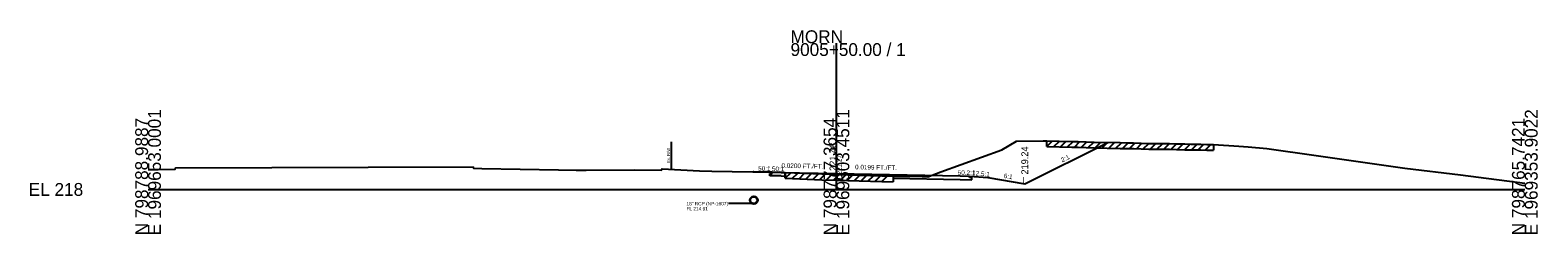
# Model space of a CAD drawing. Extents: x -26 to 2313, y -1511 to 5559.
# Drawn here: x -25.7 to 302.8, y 3490.3 to 3534.7 of the extents above; entities that cross this region are included whole.
import ezdxf

# ---------------------------------------------------------------- set-up
doc = ezdxf.new("R2010")
doc.units = 0
for name, color, linetype in [('RD_GPK_XS_Cell', 7, 'Continuous'), ('RD_XS_Base', 7, 'Continuous'), ('RD_XS_EarthShd', 7, 'Continuous'), ('RD_XS_ExGround', 7, 'Continuous'), ('RD_XS_ExPaveRet', 7, 'Continuous'), ('RD_XS_ExRW', 7, 'Continuous'), ('RD_XS_Misc_Line', 7, 'Continuous'), ('RD_XS_Pave', 7, 'Continuous'), ('RD_XS_PaveOvlay', 7, 'Continuous'), ('RD_XS_PaveShd', 7, 'Continuous'), ('RD_XS_Pipe', 7, 'Continuous'), ('RD_XS_TieSlope', 7, 'Continuous'), ('RD_XS_TX_Elev_EX', 7, 'Continuous'), ('RD_XS_TX_Elev_PR', 7, 'Continuous'), ('RD_XS_TX_Misc', 7, 'Continuous'), ('RD_XS_TX_MkPT', 7, 'Continuous'), ('RD_XS_TX_Profile', 7, 'Continuous'), ('RD_XS_TX_ShdSlope', 7, 'Continuous'), ('RD_XS_TX_Slope', 7, 'Continuous')]:
    doc.layers.add(name, color=color, linetype=linetype)

msp = doc.modelspace()

# ---------------------------------------------------------------- linework, layer by layer
at = {"layer": 'RD_GPK_XS_Cell'}
for p, q in [((150, 3500), (150, 3531.9)), ((0, 3500), (150, 3500)), ((150, 3500), (300, 3500))]:
    msp.add_line(p, q, dxfattribs=at)
at = {"layer": 'RD_XS_Base'}
for p, q in [((135.49, 3503.47), (135.99, 3503.46)), ((135.49, 3502.99), (135.49, 3503.47)), ((137.99, 3502.94), (135.49, 3502.99)), ((135.99, 3503.46), (135.99, 3503.76)), ((179, 3502.6), (179, 3502.9)), ((179.5, 3502.59), (179, 3502.6)), ((179.5, 3502.11), (179.5, 3502.59)), ((176.99, 3502.16), (179.5, 3502.11))]:
    msp.add_line(p, q, dxfattribs=at)
at = {"layer": 'RD_XS_EarthShd'}
for p, q in [((135.99, 3503.76), (131.99, 3503.84)), ((179, 3502.9), (183.01, 3502.58))]:
    msp.add_line(p, q, dxfattribs=at)
at = {"layer": 'RD_XS_ExGround'}
msp.add_lwpolyline([(0, 3504.36), (2.1, 3504.37), (5.88, 3504.41), (5.98, 3504.71), (47.94, 3504.84), (70.81, 3504.91), (70.91, 3504.61), (72.71, 3504.55), (89.45, 3504.3), (93.28, 3504.23), (95.43, 3504.22), (106.03, 3504.24), (111.89, 3504.18), (111.99, 3504.48), (120.18, 3504.09), (122.84, 3504), (136.23, 3503.73), (138.86, 3503.68), (146.81, 3503.37), (150, 3503.27), (162.34, 3502.87), (168.66, 3502.84), (169.3, 3502.79), (169.92, 3502.77), (172.72, 3503.84), (186.04, 3508.65), (189.25, 3510.5), (195.08, 3510.63), (195.85, 3510.63), (201.26, 3510.48), (202.08, 3510.46), (202.65, 3510.44), (206.18, 3510.32), (211.82, 3510.2), (213.2, 3510.17), (214.74, 3510.14), (218.05, 3510.05), (219.65, 3510), (220.11, 3510), (222.55, 3510), (224.08, 3509.96), (225.91, 3509.92), (227.3, 3509.88), (229.43, 3509.85), (230.68, 3509.82), (232.18, 3509.78), (237.65, 3509.43), (239.74, 3509.28), (243.78, 3508.92), (254.5, 3507.37), (273.82, 3504.63), (285.97, 3503.15), (300, 3501.38)], dxfattribs=at)
at = {"layer": 'RD_XS_ExPaveRet'}
for p, q in [((195.85, 3509.38), (195.85, 3510.63)), ((195.85, 3509.38), (201.26, 3509.23)), ((201.26, 3509.23), (202.08, 3509.21)), ((202.08, 3509.21), (202.65, 3509.19)), ((202.65, 3509.19), (206.18, 3509.07)), ((206.18, 3509.07), (211.82, 3508.95)), ((211.82, 3508.95), (213.2, 3508.92)), ((213.2, 3508.92), (214.74, 3508.89)), ((214.74, 3508.89), (218.05, 3508.8)), ((218.05, 3508.8), (219.65, 3508.75)), ((219.65, 3508.75), (220.11, 3508.75)), ((220.11, 3508.75), (222.55, 3508.75)), ((222.55, 3508.75), (224.08, 3508.71)), ((232.18, 3509.78), (232.18, 3508.53)), ((224.08, 3508.71), (225.91, 3508.67)), ((225.91, 3508.67), (227.3, 3508.63)), ((227.3, 3508.63), (229.43, 3508.6)), ((229.43, 3508.6), (230.68, 3508.57)), ((230.68, 3508.57), (232.18, 3508.53)), ((138.86, 3502.43), (138.86, 3503.68)), ((138.86, 3502.43), (146.81, 3502.12)), ((162.34, 3502.87), (162.34, 3501.62)), ((146.81, 3502.12), (150, 3502.02)), ((150, 3502.02), (162.34, 3501.62))]:
    msp.add_line(p, q, dxfattribs=at)
at = {"layer": 'RD_XS_ExRW'}
msp.add_line((113.97, 3510.38), (113.97, 3504.38), dxfattribs=at)
at = {"layer": 'RD_XS_Misc_Line'}
for p, q in [((195.85, 3509.38), (197.07, 3510.6)), ((197.35, 3509.34), (198.57, 3510.56)), ((198.85, 3509.3), (200.07, 3510.51)), ((200.35, 3509.26), (201.57, 3510.47)), ((201.85, 3509.22), (203.06, 3510.43)), ((203.35, 3509.17), (204.56, 3510.37)), ((204.85, 3509.11), (206.06, 3510.32)), ((206.35, 3509.07), (207.58, 3510.29)), ((207.85, 3509.03), (209.08, 3510.26)), ((209.35, 3509), (210.58, 3510.23)), ((210.85, 3508.97), (212.08, 3510.19)), ((212.35, 3508.94), (213.58, 3510.16)), ((213.85, 3508.91), (215.07, 3510.13)), ((215.35, 3508.87), (216.57, 3510.09)), ((216.85, 3508.83), (218.07, 3510.05)), ((218.35, 3508.79), (219.57, 3510)), ((219.85, 3508.75), (221.1, 3510)), ((221.35, 3508.75), (222.6, 3510)), ((222.85, 3508.74), (224.07, 3509.96)), ((224.35, 3508.71), (225.57, 3509.93)), ((225.85, 3508.67), (227.07, 3509.89)), ((227.35, 3508.63), (228.59, 3509.86)), ((228.85, 3508.61), (230.08, 3509.84)), ((230.35, 3508.58), (231.57, 3509.8)), ((138.86, 3502.43), (140.06, 3503.63)), ((140.36, 3502.37), (141.56, 3503.57)), ((141.86, 3502.31), (143.06, 3503.51)), ((143.36, 3502.25), (144.56, 3503.46)), ((144.86, 3502.19), (146.06, 3503.4)), ((146.36, 3502.14), (147.57, 3503.34)), ((147.86, 3502.08), (149.07, 3503.3)), ((149.36, 3502.04), (150.57, 3503.25)), ((150.86, 3501.99), (152.07, 3503.2)), ((152.36, 3501.94), (153.57, 3503.15)), ((153.86, 3501.89), (155.07, 3503.1)), ((155.36, 3501.84), (156.57, 3503.05)), ((156.86, 3501.79), (158.07, 3503)), ((158.36, 3501.75), (159.57, 3502.96)), ((159.86, 3501.7), (161.07, 3502.91))]:
    msp.add_line(p, q, dxfattribs=at)
at = {"layer": 'RD_XS_Pave'}
for p, q in [((137.99, 3503.72), (150, 3503.48)), ((137.99, 3502.94), (138.86, 3502.92)), ((150, 3503.48), (176.99, 3502.94)), ((162.34, 3502.45), (176.99, 3502.16))]:
    msp.add_line(p, q, dxfattribs=at)
at = {"layer": 'RD_XS_PaveOvlay'}
for p, q in [((138.86, 3503.69), (146.81, 3503.38)), ((138.86, 3503.69), (138.86, 3502.92)), ((146.81, 3503.38), (150, 3503.28)), ((150, 3503.28), (162.34, 3502.88)), ((162.34, 3502.88), (162.34, 3502.45))]:
    msp.add_line(p, q, dxfattribs=at)
at = {"layer": 'RD_XS_PaveShd'}
for p, q in [((137.99, 3503.72), (135.99, 3503.76)), ((176.99, 3502.94), (179, 3502.9))]:
    msp.add_line(p, q, dxfattribs=at)
at = {"layer": 'RD_XS_Pipe'}
msp.add_line((131.49, 3496.91), (126.49, 3496.91), dxfattribs=at)
for radius in [0.85, 0.75]:
    msp.add_circle((131.99, 3497.66), radius, dxfattribs=at)
at = {"layer": 'RD_XS_TieSlope'}
for p, q in [((191.04, 3501.24), (209.12, 3510.26)), ((131.99, 3503.84), (131.87, 3503.82)), ((183.01, 3502.58), (191.04, 3501.24))]:
    msp.add_line(p, q, dxfattribs=at)

# ---------------------------------------------------------------- texts
at = {"layer": 'RD_GPK_XS_Cell'}
for s, p in [('9005+50.00 / 1', (140, 3529.1)), ('MORN', (140, 3531.9)), ('EL 218', (-26, 3498.6))]:
    msp.add_text(s, height=2.8, dxfattribs=at).set_placement(p)
for s, p in [('N 798788.9887', (0, 3490)), ('E 1969653.0001', (2.8, 3490)), ('N 798777.3654', (150, 3490)), ('E 1969503.4511', (152.8, 3490)), ('N 798765.7421', (300, 3490)), ('E 1969353.9022', (302.8, 3490))]:
    msp.add_text(s, height=2.8, rotation=90, dxfattribs=at).set_placement(p)
at = {"layer": 'RD_XS_ExRW'}
msp.add_text('Ex. R/W ', height=0.65, rotation=90, dxfattribs=at).set_placement((113.72, 3505.77))
at = {"layer": 'RD_XS_Pipe'}
for s, p in [('18" RCP (NP-1607)', (117.32, 3496.53)), ('FL 214.91', (117.32, 3495.41))]:
    msp.add_text(s, height=0.75, dxfattribs=at).set_placement(p)
at = {"layer": 'RD_XS_TX_Elev_EX'}
msp.add_text('221.27', height=1, rotation=90, dxfattribs=at).set_placement((151.13, 3503.27))
at = {"layer": 'RD_XS_TX_Elev_PR'}
msp.add_text(' 221.48', height=1.5, rotation=90, dxfattribs=at).set_placement((150, 3503.48))
at = {"layer": 'RD_XS_TX_Misc'}
msp.add_text('219.24', height=1.5, rotation=90, dxfattribs=at).set_placement((191.79, 3503.24))
at = {"layer": 'RD_XS_TX_MkPT'}
msp.add_text('L', height=1.5, dxfattribs=at).set_placement((190.53, 3501.24))
at = {"layer": 'RD_XS_TX_Profile'}
for s, rotation, p in [('50:1', 358.8542, (135.94, 3504.01)), ('50.2:1', 358.858, (176.42, 3503.2))]:
    msp.add_text(s, height=1, rotation=rotation, dxfattribs=at).set_placement(p)
at = {"layer": 'RD_XS_TX_ShdSlope'}
for s, rotation, p in [('50:1', 358.8542, (132.94, 3504.07)), ('12.5:1', 355.4411, (179.55, 3503.1))]:
    msp.add_text(s, height=1, rotation=rotation, dxfattribs=at).set_placement(p)
at = {"layer": 'RD_XS_TX_Slope'}
for s, rotation, p in [('0.0200 FT./FT.', 358.8542, (138.02, 3504.72)), ('2:1', 26.4894, (199.22, 3505.88)), ('0.0199 FT./FT.', 358.858, (154.06, 3504.4)), ('6:1', 350.5683, (186.41, 3502.52))]:
    msp.add_text(s, height=1, rotation=rotation, dxfattribs=at).set_placement(p)

doc.saveas('drawing.dxf')
